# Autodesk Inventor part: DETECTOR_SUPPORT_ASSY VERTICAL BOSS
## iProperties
Shininess: 64.0
Length Units: 11272
Angle Units: 11279
Time Units: 11290
Mass Units: 11286
Length Display Precision: 3
Angle Display Precision: 2
Compacted: True
Part Number: DETECTOR_SUPPORT_ASSY VERTICAL BOSS
Document SubType Name: Modeling
Created: 2004-08
Designer: John Blackburn
Material: MILD_STEEL
Manufacturer: Standard
Standards Organization: Custom
Density: 0.0
Volumn: 0.0
Area: 0.0
PropertySet Name: Model Information
Control State: 0
Master: False
Checked Out: False
Author: John Blackburn
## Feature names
1. ExtrusionBlind1
2. AM_HOLE_SI0030_1 [Hole]
3. RevolutionAngle1
